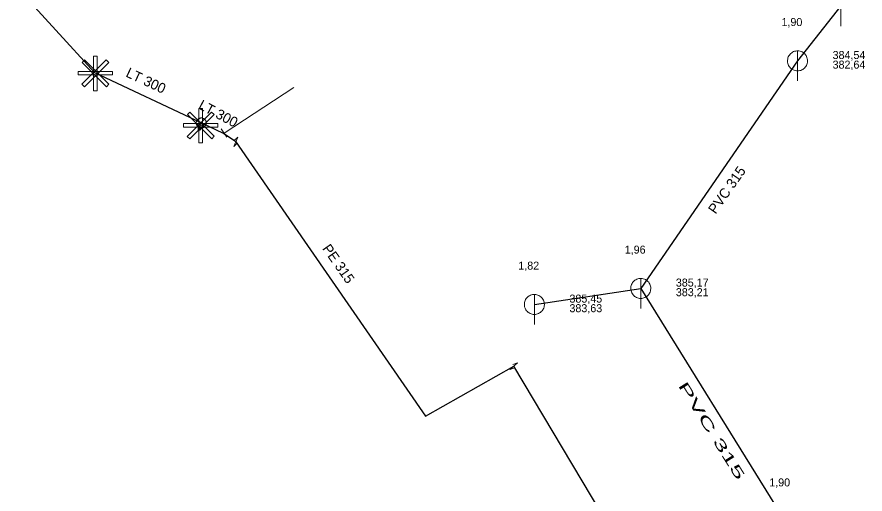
# Model space of a CAD drawing. Extents: x -809028 to -807737, y -990545 to -989489.
# Drawn here: x -808131.3 to -808046.5, y -989961.2 to -989913.5 of the extents above; entities that cross this region are included whole.
import ezdxf

# ---------------------------------------------------------------- set-up
doc = ezdxf.new("R2010")
doc.units = 0
doc.header["$LTSCALE"] = 0.32
for name, color, linetype, lineweight in [('1', 7, 'Continuous', 13), ('12', 7, 'Continuous', 13), ('13', 7, 'Continuous', 13), ('14', 7, 'Continuous', 25), ('17', 7, 'Continuous', 25), ('22', 7, 'Continuous', 13), ('34', 7, 'Continuous', 13), ('47', 7, 'Continuous', 13), ('9', 7, 'Continuous', 13)]:
    doc.layers.add(name, color=color, linetype=linetype, lineweight=lineweight)

msp = doc.modelspace()

# ---------------------------------------------------------------- linework, layer by layer
at = {"layer": '12'}
for points in [[(-808122.348, -989917.83), (-808122.1, -989918.078), (-808124.529, -989920.507), (-808124.776, -989920.259)], [(-808124.767, -989918.069), (-808124.52, -989917.821), (-808122.091, -989920.25), (-808122.338, -989920.498)], [(-808123.614, -989917.466), (-808123.264, -989917.466), (-808123.264, -989920.901), (-808123.614, -989920.901)], [(-808121.73, -989918.975), (-808121.73, -989919.325), (-808125.165, -989919.325), (-808125.165, -989918.975)], [(-808113.091, -989922.674), (-808112.74, -989922.674), (-808112.74, -989926.109), (-808113.091, -989926.109)], [(-808111.825, -989923.038), (-808111.576, -989923.286), (-808114.005, -989925.715), (-808114.252, -989925.467)], [(-808114.244, -989923.277), (-808113.997, -989923.029), (-808111.568, -989925.458), (-808111.815, -989925.706)], [(-808111.206, -989924.183), (-808111.206, -989924.533), (-808114.642, -989924.533), (-808114.642, -989924.183)]]:
    msp.add_lwpolyline(points, close=True, dxfattribs=at)
at = {"layer": '13'}
msp.add_line((-808110.582, -989925.138), (-808103.6, -989920.579), dxfattribs=at)
at = {"layer": '14'}
for p, q in [((-808048.949, -989912.44), (-808053.289, -989917.92)), ((-808053.289, -989917.92), (-808068.949, -989940.649)), ((-808079.579, -989942.25), (-808068.949, -989940.649)), ((-808068.949, -989940.649), (-808054.51, -989963.899))]:
    msp.add_line(p, q, dxfattribs=at)
at = {"layer": '14', "lineweight": 13}
for p, q in [((-808112.933, -989924.359), (-808113.05, -989924.731)), ((-808112.855, -989924.124), (-808112.933, -989924.359)), ((-808110.625, -989925.171), (-808110.582, -989925.138))]:
    msp.add_line(p, q, dxfattribs=at)
at = {"layer": '17'}
msp.add_line((-808054.229, -989994.256), (-808081.64, -989948.42), dxfattribs=at)
for points in [[(-808112.855, -989924.124), (-808123.5, -989919.131), (-808131.269, -989910.559)], [(-808109.39, -989926), (-808110.625, -989925.171), (-808112.855, -989924.124)], [(-808109.39, -989926), (-808090.44, -989953.399), (-808081.64, -989948.42)]]:
    msp.add_lwpolyline(points, dxfattribs=at)
at = {"layer": '22'}
for p, q in [((-808048.949, -989914.44), (-808048.948, -989911.44)), ((-808053.289, -989919.92), (-808053.288, -989916.92)), ((-808068.949, -989942.649), (-808068.948, -989939.649)), ((-808079.579, -989944.25), (-808079.578, -989941.25))]:
    msp.add_line(p, q, dxfattribs=at)
for points in [[(-808052.289, -989917.92), (-808052.294, -989917.811), (-808052.312, -989917.703), (-808052.342, -989917.597), (-808052.382, -989917.496), (-808052.434, -989917.399), (-808052.496, -989917.309), (-808052.568, -989917.226), (-808052.648, -989917.152), (-808052.736, -989917.086), (-808052.83, -989917.031), (-808052.93, -989916.986), (-808053.035, -989916.953), (-808053.142, -989916.931), (-808053.251, -989916.921), (-808053.361, -989916.923), (-808053.469, -989916.937), (-808053.576, -989916.962), (-808053.679, -989916.999), (-808053.777, -989917.048), (-808053.869, -989917.106), (-808053.955, -989917.175), (-808054.032, -989917.252), (-808054.101, -989917.338), (-808054.16, -989917.43), (-808054.208, -989917.528), (-808054.245, -989917.631), (-808054.271, -989917.738), (-808054.285, -989917.846), (-808054.288, -989917.956), (-808054.278, -989918.065), (-808054.257, -989918.172), (-808054.223, -989918.276), (-808054.179, -989918.376), (-808054.124, -989918.471), (-808054.058, -989918.559), (-808053.984, -989918.639), (-808053.901, -989918.711), (-808053.811, -989918.773), (-808053.715, -989918.825), (-808053.613, -989918.866), (-808053.508, -989918.896), (-808053.4, -989918.914), (-808053.29, -989918.92), (-808053.181, -989918.914), (-808053.073, -989918.896), (-808052.968, -989918.867), (-808052.866, -989918.826), (-808052.769, -989918.774), (-808052.679, -989918.712), (-808052.596, -989918.641), (-808052.521, -989918.561), (-808052.456, -989918.473), (-808052.4, -989918.379), (-808052.356, -989918.279), (-808052.322, -989918.175), (-808052.3, -989918.067), (-808052.29, -989917.958)], [(-808067.949, -989940.649), (-808067.954, -989940.54), (-808067.972, -989940.432), (-808068.002, -989940.326), (-808068.042, -989940.225), (-808068.094, -989940.128), (-808068.156, -989940.038), (-808068.228, -989939.955), (-808068.308, -989939.881), (-808068.396, -989939.815), (-808068.49, -989939.76), (-808068.59, -989939.715), (-808068.695, -989939.682), (-808068.802, -989939.66), (-808068.911, -989939.65), (-808069.021, -989939.652), (-808069.129, -989939.666), (-808069.236, -989939.691), (-808069.339, -989939.728), (-808069.437, -989939.777), (-808069.529, -989939.835), (-808069.615, -989939.904), (-808069.692, -989939.981), (-808069.761, -989940.067), (-808069.82, -989940.159), (-808069.868, -989940.257), (-808069.905, -989940.36), (-808069.931, -989940.467), (-808069.945, -989940.575), (-808069.948, -989940.685), (-808069.938, -989940.794), (-808069.917, -989940.901), (-808069.883, -989941.005), (-808069.839, -989941.105), (-808069.784, -989941.2), (-808069.718, -989941.288), (-808069.644, -989941.368), (-808069.561, -989941.44), (-808069.471, -989941.502), (-808069.375, -989941.554), (-808069.273, -989941.595), (-808069.168, -989941.625), (-808069.06, -989941.643), (-808068.95, -989941.649), (-808068.841, -989941.643), (-808068.733, -989941.625), (-808068.628, -989941.596), (-808068.526, -989941.555), (-808068.429, -989941.503), (-808068.339, -989941.441), (-808068.256, -989941.37), (-808068.181, -989941.29), (-808068.116, -989941.202), (-808068.06, -989941.108), (-808068.016, -989941.008), (-808067.982, -989940.904), (-808067.96, -989940.796), (-808067.95, -989940.687)], [(-808078.579, -989942.25), (-808078.584, -989942.141), (-808078.602, -989942.033), (-808078.632, -989941.927), (-808078.672, -989941.826), (-808078.724, -989941.729), (-808078.786, -989941.639), (-808078.858, -989941.556), (-808078.938, -989941.482), (-808079.026, -989941.416), (-808079.12, -989941.361), (-808079.22, -989941.316), (-808079.325, -989941.283), (-808079.432, -989941.261), (-808079.541, -989941.251), (-808079.651, -989941.253), (-808079.759, -989941.267), (-808079.866, -989941.292), (-808079.969, -989941.329), (-808080.067, -989941.378), (-808080.159, -989941.436), (-808080.245, -989941.505), (-808080.322, -989941.582), (-808080.391, -989941.668), (-808080.45, -989941.76), (-808080.498, -989941.858), (-808080.535, -989941.961), (-808080.561, -989942.068), (-808080.575, -989942.176), (-808080.578, -989942.286), (-808080.568, -989942.395), (-808080.547, -989942.502), (-808080.513, -989942.606), (-808080.469, -989942.706), (-808080.414, -989942.801), (-808080.348, -989942.889), (-808080.274, -989942.969), (-808080.191, -989943.041), (-808080.101, -989943.103), (-808080.005, -989943.155), (-808079.903, -989943.196), (-808079.798, -989943.226), (-808079.69, -989943.244), (-808079.58, -989943.25), (-808079.471, -989943.244), (-808079.363, -989943.226), (-808079.258, -989943.197), (-808079.156, -989943.156), (-808079.059, -989943.104), (-808078.969, -989943.042), (-808078.886, -989942.971), (-808078.811, -989942.891), (-808078.746, -989942.803), (-808078.69, -989942.709), (-808078.646, -989942.609), (-808078.612, -989942.505), (-808078.59, -989942.397), (-808078.58, -989942.288)]]:
    msp.add_lwpolyline(points, close=True, dxfattribs=at)
at = {"layer": '34'}
for p, q in [((-808112.455, -989924.507), (-808113.41, -989924.209)), ((-808110.855, -989924.719), (-808110.309, -989925.556))]:
    msp.add_line(p, q, dxfattribs=at)
at = {"layer": '47'}
for p, q in [((-808109.587, -989926.469), (-808109.223, -989926.112)), ((-808082.018, -989948.76), (-808081.536, -989948.592))]:
    msp.add_line(p, q, dxfattribs=at)
for points in [[(-808113.307, -989923.911), (-808113.327, -989923.96), (-808113.341, -989924.01), (-808113.35, -989924.061), (-808113.354, -989924.113), (-808113.353, -989924.166), (-808113.345, -989924.218), (-808113.332, -989924.268), (-808113.314, -989924.318), (-808113.292, -989924.364), (-808113.265, -989924.409), (-808113.232, -989924.451), (-808113.196, -989924.488), (-808113.156, -989924.522), (-808113.113, -989924.551), (-808113.067, -989924.576), (-808113.018, -989924.596), (-808112.968, -989924.61), (-808112.916, -989924.619), (-808112.865, -989924.623), (-808112.812, -989924.622), (-808112.76, -989924.614), (-808112.709, -989924.602), (-808112.66, -989924.584), (-808112.613, -989924.562), (-808112.569, -989924.534), (-808112.527, -989924.501), (-808112.489, -989924.465), (-808112.456, -989924.425), (-808112.427, -989924.382), (-808112.402, -989924.336), (-808112.382, -989924.287), (-808112.368, -989924.237), (-808112.358, -989924.185), (-808112.355, -989924.134), (-808112.356, -989924.081), (-808112.363, -989924.029), (-808112.375, -989923.978), (-808112.393, -989923.929), (-808112.416, -989923.882), (-808112.444, -989923.838), (-808112.477, -989923.796), (-808112.512, -989923.758), (-808112.553, -989923.725), (-808112.596, -989923.696), (-808112.642, -989923.671), (-808112.691, -989923.651), (-808112.741, -989923.637), (-808112.792, -989923.627), (-808112.844, -989923.624), (-808112.897, -989923.625), (-808112.949, -989923.632), (-808112.999, -989923.645), (-808113.048, -989923.663), (-808113.095, -989923.686), (-808113.14, -989923.713), (-808113.182, -989923.746), (-808113.219, -989923.781), (-808113.253, -989923.822), (-808113.282, -989923.865)], [(-808112.929, -989924.089), (-808112.933, -989924.097), (-808112.934, -989924.105), (-808112.936, -989924.113), (-808112.936, -989924.122), (-808112.936, -989924.13), (-808112.935, -989924.139), (-808112.933, -989924.147), (-808112.93, -989924.155), (-808112.926, -989924.163), (-808112.922, -989924.17), (-808112.916, -989924.177), (-808112.91, -989924.184), (-808112.904, -989924.189), (-808112.897, -989924.194), (-808112.889, -989924.198), (-808112.881, -989924.202), (-808112.873, -989924.203), (-808112.865, -989924.205), (-808112.856, -989924.205), (-808112.848, -989924.205), (-808112.839, -989924.204), (-808112.831, -989924.202), (-808112.823, -989924.199), (-808112.814, -989924.195), (-808112.808, -989924.191), (-808112.801, -989924.185), (-808112.794, -989924.179), (-808112.789, -989924.173), (-808112.784, -989924.166), (-808112.78, -989924.158), (-808112.776, -989924.15), (-808112.775, -989924.142), (-808112.773, -989924.134), (-808112.773, -989924.125), (-808112.773, -989924.117), (-808112.773, -989924.108), (-808112.776, -989924.1), (-808112.779, -989924.092), (-808112.783, -989924.083), (-808112.787, -989924.077), (-808112.793, -989924.07), (-808112.799, -989924.063), (-808112.805, -989924.058), (-808112.812, -989924.053), (-808112.82, -989924.049), (-808112.828, -989924.045), (-808112.836, -989924.044), (-808112.844, -989924.042), (-808112.853, -989924.042), (-808112.861, -989924.042), (-808112.87, -989924.042), (-808112.878, -989924.045), (-808112.886, -989924.048), (-808112.894, -989924.052), (-808112.901, -989924.056), (-808112.908, -989924.062), (-808112.915, -989924.068), (-808112.92, -989924.074), (-808112.925, -989924.081)]]:
    msp.add_lwpolyline(points, close=True, dxfattribs=at)
for points in [[(-808109.587, -989926.469), (-808109.192, -989925.53), (-808109.556, -989925.887)], [(-808082.018, -989948.76), (-808081.261, -989948.079), (-808081.743, -989948.247)]]:
    msp.add_lwpolyline(points, dxfattribs=at)
at = {"layer": '9'}
for points in [[(-808113.176, -989924.731), (-808113.176, -989924.744), (-808113.174, -989924.757), (-808113.171, -989924.77), (-808113.166, -989924.782), (-808113.16, -989924.794), (-808113.153, -989924.805), (-808113.145, -989924.815), (-808113.135, -989924.825), (-808113.125, -989924.833), (-808113.114, -989924.84), (-808113.102, -989924.846), (-808113.09, -989924.851), (-808113.077, -989924.854), (-808113.064, -989924.856), (-808113.051, -989924.858), (-808113.038, -989924.857), (-808113.025, -989924.855), (-808113.012, -989924.852), (-808113, -989924.847), (-808112.988, -989924.841), (-808112.977, -989924.834), (-808112.967, -989924.826), (-808112.957, -989924.816), (-808112.949, -989924.806), (-808112.942, -989924.795), (-808112.936, -989924.783), (-808112.931, -989924.771), (-808112.928, -989924.758), (-808112.926, -989924.745), (-808112.924, -989924.732), (-808112.925, -989924.719), (-808112.927, -989924.706), (-808112.93, -989924.693), (-808112.935, -989924.681), (-808112.941, -989924.669), (-808112.948, -989924.658), (-808112.956, -989924.648), (-808112.966, -989924.638), (-808112.976, -989924.63), (-808112.987, -989924.623), (-808112.999, -989924.617), (-808113.011, -989924.612), (-808113.024, -989924.609), (-808113.037, -989924.607), (-808113.05, -989924.606), (-808113.063, -989924.606), (-808113.076, -989924.608), (-808113.089, -989924.611), (-808113.101, -989924.616), (-808113.113, -989924.622), (-808113.124, -989924.629), (-808113.134, -989924.637), (-808113.144, -989924.647), (-808113.152, -989924.657), (-808113.159, -989924.668), (-808113.165, -989924.68), (-808113.17, -989924.692), (-808113.173, -989924.705), (-808113.175, -989924.718)], [(-808113.156, -989924.731), (-808113.157, -989924.742), (-808113.155, -989924.753), (-808113.152, -989924.764), (-808113.148, -989924.774), (-808113.143, -989924.784), (-808113.137, -989924.793), (-808113.13, -989924.802), (-808113.122, -989924.81), (-808113.113, -989924.817), (-808113.104, -989924.823), (-808113.094, -989924.828), (-808113.084, -989924.832), (-808113.073, -989924.835), (-808113.062, -989924.838), (-808113.051, -989924.838), (-808113.04, -989924.838), (-808113.029, -989924.836), (-808113.018, -989924.833), (-808113.008, -989924.829), (-808112.998, -989924.824), (-808112.989, -989924.818), (-808112.98, -989924.811), (-808112.972, -989924.803), (-808112.965, -989924.794), (-808112.959, -989924.785), (-808112.954, -989924.775), (-808112.95, -989924.765), (-808112.947, -989924.754), (-808112.945, -989924.743), (-808112.944, -989924.732), (-808112.944, -989924.721), (-808112.946, -989924.71), (-808112.949, -989924.699), (-808112.953, -989924.689), (-808112.958, -989924.679), (-808112.964, -989924.67), (-808112.971, -989924.661), (-808112.979, -989924.653), (-808112.988, -989924.646), (-808112.997, -989924.64), (-808113.007, -989924.635), (-808113.017, -989924.631), (-808113.028, -989924.628), (-808113.039, -989924.626), (-808113.05, -989924.626), (-808113.061, -989924.625), (-808113.072, -989924.627), (-808113.083, -989924.63), (-808113.093, -989924.634), (-808113.103, -989924.639), (-808113.112, -989924.645), (-808113.121, -989924.652), (-808113.129, -989924.66), (-808113.136, -989924.669), (-808113.142, -989924.678), (-808113.147, -989924.688), (-808113.151, -989924.698), (-808113.154, -989924.709), (-808113.156, -989924.72)], [(-808113.137, -989924.731), (-808113.137, -989924.74), (-808113.136, -989924.749), (-808113.133, -989924.758), (-808113.13, -989924.766), (-808113.126, -989924.774), (-808113.121, -989924.782), (-808113.115, -989924.789), (-808113.109, -989924.795), (-808113.102, -989924.801), (-808113.094, -989924.806), (-808113.086, -989924.81), (-808113.078, -989924.813), (-808113.069, -989924.816), (-808113.06, -989924.817), (-808113.051, -989924.819), (-808113.042, -989924.818), (-808113.033, -989924.817), (-808113.024, -989924.814), (-808113.016, -989924.811), (-808113.008, -989924.807), (-808113, -989924.802), (-808112.993, -989924.796), (-808112.987, -989924.79), (-808112.981, -989924.783), (-808112.976, -989924.775), (-808112.972, -989924.767), (-808112.969, -989924.759), (-808112.966, -989924.75), (-808112.965, -989924.741), (-808112.963, -989924.732), (-808112.964, -989924.723), (-808112.965, -989924.714), (-808112.968, -989924.705), (-808112.971, -989924.697), (-808112.975, -989924.689), (-808112.98, -989924.681), (-808112.986, -989924.674), (-808112.992, -989924.668), (-808112.999, -989924.662), (-808113.007, -989924.657), (-808113.015, -989924.653), (-808113.023, -989924.65), (-808113.032, -989924.647), (-808113.041, -989924.646), (-808113.05, -989924.645), (-808113.059, -989924.645), (-808113.068, -989924.646), (-808113.077, -989924.649), (-808113.085, -989924.652), (-808113.093, -989924.656), (-808113.101, -989924.661), (-808113.108, -989924.667), (-808113.114, -989924.673), (-808113.12, -989924.68), (-808113.125, -989924.688), (-808113.129, -989924.696), (-808113.132, -989924.704), (-808113.135, -989924.713), (-808113.136, -989924.722)], [(-808113.117, -989924.731), (-808113.117, -989924.738), (-808113.116, -989924.745), (-808113.115, -989924.752), (-808113.112, -989924.758), (-808113.109, -989924.764), (-808113.105, -989924.77), (-808113.101, -989924.776), (-808113.096, -989924.781), (-808113.09, -989924.785), (-808113.084, -989924.789), (-808113.078, -989924.792), (-808113.072, -989924.795), (-808113.065, -989924.796), (-808113.058, -989924.799), (-808113.051, -989924.799), (-808113.044, -989924.799), (-808113.037, -989924.797), (-808113.03, -989924.796), (-808113.024, -989924.793), (-808113.017, -989924.79), (-808113.012, -989924.786), (-808113.006, -989924.782), (-808113.001, -989924.777), (-808112.997, -989924.771), (-808112.993, -989924.765), (-808112.99, -989924.759), (-808112.987, -989924.753), (-808112.985, -989924.746), (-808112.984, -989924.739), (-808112.983, -989924.732), (-808112.983, -989924.725), (-808112.984, -989924.718), (-808112.986, -989924.711), (-808112.989, -989924.705), (-808112.992, -989924.698), (-808112.996, -989924.693), (-808113, -989924.687), (-808113.005, -989924.682), (-808113.011, -989924.678), (-808113.016, -989924.674), (-808113.023, -989924.671), (-808113.029, -989924.668), (-808113.036, -989924.666), (-808113.043, -989924.665), (-808113.05, -989924.665), (-808113.057, -989924.665), (-808113.064, -989924.665), (-808113.071, -989924.667), (-808113.077, -989924.67), (-808113.083, -989924.673), (-808113.089, -989924.677), (-808113.095, -989924.681), (-808113.1, -989924.686), (-808113.104, -989924.692), (-808113.108, -989924.697), (-808113.111, -989924.704), (-808113.114, -989924.71), (-808113.115, -989924.717), (-808113.117, -989924.724)], [(-808113.097, -989924.731), (-808113.097, -989924.736), (-808113.097, -989924.741), (-808113.096, -989924.746), (-808113.094, -989924.75), (-808113.092, -989924.755), (-808113.089, -989924.759), (-808113.086, -989924.762), (-808113.082, -989924.766), (-808113.079, -989924.769), (-808113.075, -989924.772), (-808113.07, -989924.774), (-808113.066, -989924.776), (-808113.061, -989924.777), (-808113.056, -989924.779), (-808113.051, -989924.779), (-808113.046, -989924.779), (-808113.041, -989924.778), (-808113.036, -989924.777), (-808113.032, -989924.775), (-808113.027, -989924.773), (-808113.023, -989924.77), (-808113.019, -989924.767), (-808113.016, -989924.763), (-808113.013, -989924.76), (-808113.01, -989924.756), (-808113.008, -989924.751), (-808113.006, -989924.747), (-808113.005, -989924.742), (-808113.004, -989924.737), (-808113.003, -989924.732), (-808113.003, -989924.727), (-808113.004, -989924.722), (-808113.005, -989924.717), (-808113.007, -989924.713), (-808113.009, -989924.708), (-808113.012, -989924.704), (-808113.015, -989924.7), (-808113.018, -989924.697), (-808113.022, -989924.694), (-808113.026, -989924.691), (-808113.031, -989924.689), (-808113.035, -989924.687), (-808113.04, -989924.686), (-808113.045, -989924.685), (-808113.05, -989924.685), (-808113.055, -989924.685), (-808113.06, -989924.686), (-808113.065, -989924.686), (-808113.069, -989924.688), (-808113.074, -989924.69), (-808113.078, -989924.693), (-808113.081, -989924.696), (-808113.085, -989924.699), (-808113.088, -989924.703), (-808113.091, -989924.707), (-808113.093, -989924.712), (-808113.095, -989924.716), (-808113.096, -989924.721), (-808113.097, -989924.726)], [(-808113.077, -989924.731), (-808113.077, -989924.734), (-808113.078, -989924.737), (-808113.077, -989924.739), (-808113.076, -989924.742), (-808113.075, -989924.745), (-808113.073, -989924.747), (-808113.071, -989924.749), (-808113.069, -989924.751), (-808113.067, -989924.753), (-808113.065, -989924.755), (-808113.062, -989924.757), (-808113.059, -989924.758), (-808113.057, -989924.758), (-808113.054, -989924.759), (-808113.051, -989924.759), (-808113.048, -989924.759), (-808113.045, -989924.759), (-808113.042, -989924.758), (-808113.04, -989924.757), (-808113.037, -989924.756), (-808113.035, -989924.754), (-808113.032, -989924.752), (-808113.03, -989924.75), (-808113.029, -989924.748), (-808113.027, -989924.746), (-808113.026, -989924.743), (-808113.024, -989924.74), (-808113.024, -989924.738), (-808113.023, -989924.735), (-808113.022, -989924.732), (-808113.023, -989924.729), (-808113.023, -989924.726), (-808113.024, -989924.723), (-808113.025, -989924.721), (-808113.026, -989924.718), (-808113.028, -989924.716), (-808113.029, -989924.713), (-808113.031, -989924.711), (-808113.034, -989924.71), (-808113.036, -989924.708), (-808113.039, -989924.707), (-808113.041, -989924.706), (-808113.044, -989924.705), (-808113.047, -989924.705), (-808113.05, -989924.704), (-808113.053, -989924.705), (-808113.056, -989924.704), (-808113.058, -989924.706), (-808113.061, -989924.706), (-808113.064, -989924.707), (-808113.066, -989924.709), (-808113.068, -989924.71), (-808113.07, -989924.712), (-808113.072, -989924.715), (-808113.074, -989924.717), (-808113.075, -989924.72), (-808113.076, -989924.722), (-808113.077, -989924.725), (-808113.077, -989924.728)], [(-808113.058, -989924.731), (-808113.058, -989924.733), (-808113.058, -989924.733), (-808113.057, -989924.733), (-808113.057, -989924.735), (-808113.058, -989924.736), (-808113.056, -989924.736), (-808113.056, -989924.736), (-808113.056, -989924.738), (-808113.056, -989924.738), (-808113.055, -989924.739), (-808113.053, -989924.739), (-808113.053, -989924.739), (-808113.053, -989924.74), (-808113.051, -989924.74), (-808113.051, -989924.74), (-808113.05, -989924.74), (-808113.049, -989924.74), (-808113.049, -989924.739), (-808113.048, -989924.739), (-808113.046, -989924.739), (-808113.046, -989924.738), (-808113.046, -989924.738), (-808113.045, -989924.737), (-808113.045, -989924.737), (-808113.043, -989924.736), (-808113.043, -989924.735), (-808113.042, -989924.734), (-808113.042, -989924.734), (-808113.042, -989924.733), (-808113.042, -989924.732), (-808113.042, -989924.731), (-808113.042, -989924.73), (-808113.042, -989924.73), (-808113.043, -989924.729), (-808113.043, -989924.728), (-808113.044, -989924.727), (-808113.044, -989924.727), (-808113.045, -989924.726), (-808113.045, -989924.726), (-808113.046, -989924.725), (-808113.047, -989924.725), (-808113.048, -989924.724), (-808113.048, -989924.724), (-808113.049, -989924.724), (-808113.05, -989924.724), (-808113.051, -989924.724), (-808113.052, -989924.724), (-808113.052, -989924.724), (-808113.053, -989924.725), (-808113.054, -989924.724), (-808113.055, -989924.726), (-808113.055, -989924.726), (-808113.056, -989924.726), (-808113.056, -989924.726), (-808113.057, -989924.728), (-808113.057, -989924.729), (-808113.057, -989924.73), (-808113.058, -989924.73), (-808113.058, -989924.731)]]:
    msp.add_lwpolyline(points, close=True, dxfattribs=at)

# ---------------------------------------------------------------- texts
at = {"layer": '1'}
for s, p in [('1,90', (-808054.889, -989914.444)), ('1,96', (-808070.549, -989937.174)), ('1,82', (-808081.18, -989938.774)), ('1,90', (-808056.11, -989960.424))]:
    msp.add_text(s, height=0.8, dxfattribs=at).set_placement(p)
for s, rotation, p in [('LT 300', 335, (-808120.474, -989919.461)), ('LT 300', 332, (-808113.224, -989922.643)), ('PVC 315 ', 55, (-808061.469, -989933.292)), ('PE 315', 305, (-808100.81, -989936.672))]:
    msp.add_text(s, height=1, rotation=rotation, dxfattribs=at).set_placement(p)
at = {"layer": '1', "width": 2.1}
msp.add_text('PVC 315 ', height=1, rotation=302, dxfattribs=at).set_placement((-808065.262, -989950.348))
at = {"layer": '14'}
for s, p in [('384,54', (-808049.783, -989917.736)), ('382,64', (-808049.783, -989918.696)), ('385,17', (-808065.443, -989940.466)), ('383,21', (-808065.443, -989941.426)), ('385,45', (-808076.073, -989942.066)), ('383,63', (-808076.073, -989943.026))]:
    msp.add_text(s, height=0.8, dxfattribs=at).set_placement(p)

doc.saveas('drawing.dxf')
